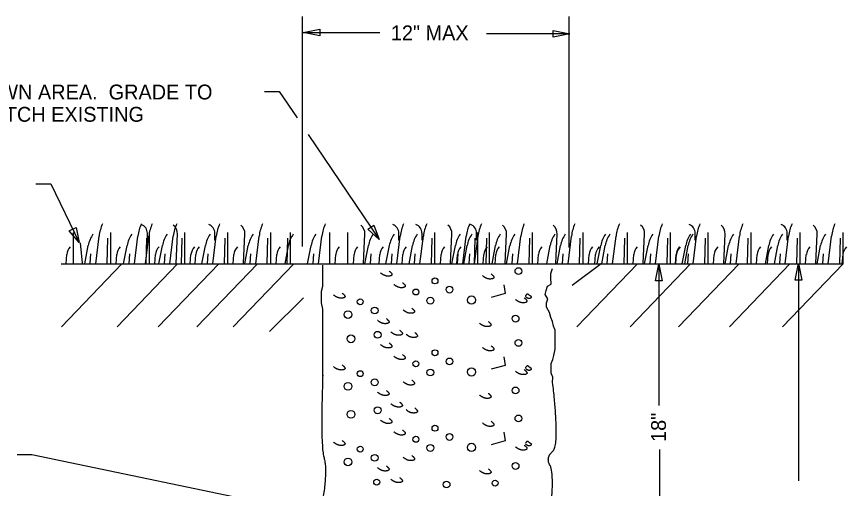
# Model space of a CAD drawing. Extents: x 10310.4 to 10401.1, y 10100.5 to 10143.6.
# Drawn here: x 10360.35 to 10397.58, y 10122.44 to 10143.62 of the extents above; entities that cross this region are included whole.
import ezdxf

# ---------------------------------------------------------------- set-up
doc = ezdxf.new("R2010")
doc.units = 0
for name, color, linetype in [('G-ANNO-TEXT', 7, 'Continuous'), ('G-DETL-LINE', 7, 'Continuous'), ('G-DETL-PATT', 7, 'Continuous')]:
    doc.layers.add(name, color=color, linetype=linetype)

msp = doc.modelspace()

# ---------------------------------------------------------------- linework, layer by layer
at = {"layer": 'G-ANNO-TEXT'}
for p, q in [((10373.185, 10133.298), (10373.185, 10143.615)), ((10385.137, 10133.255), (10385.137, 10143.615)), ((10373.209, 10142.899), (10376.655, 10142.899)), ((10385.175, 10142.836), (10381.434, 10142.836)), ((10371.471, 10140.249), (10372.138, 10140.249)), ((10372.138, 10140.249), (10372.935, 10139.065)), ((10373.435, 10138.323), (10376.614, 10133.607)), ((10361.22, 10136.112), (10361.887, 10136.112)), ((10361.887, 10136.112), (10363.16, 10133.474)), ((10389.164, 10132.497), (10389.164, 10126.153)), ((10395.422, 10132.539), (10395.422, 10122.775)), ((10389.206, 10120.468), (10389.206, 10124.176)), ((10360.378, 10123.964), (10361.045, 10123.964)), ((10361.045, 10123.964), (10377.733, 10120.481))]:
    msp.add_line(p, q, dxfattribs=at)
for points in [[(10373.959, 10142.749), (10373.209, 10142.899), (10373.959, 10143.049)], [(10384.425, 10142.986), (10385.175, 10142.836), (10384.425, 10142.686)], [(10376.38, 10134.253), (10376.614, 10133.607), (10376.103, 10134.067)], [(10363.02, 10134.147), (10363.16, 10133.474), (10362.72, 10134.002)], [(10389.014, 10131.747), (10389.164, 10132.497), (10389.314, 10131.747)], [(10395.272, 10131.789), (10395.422, 10132.539), (10395.572, 10131.789)]]:
    msp.add_lwpolyline(points, close=True, dxfattribs=at)
at = {"layer": 'G-DETL-LINE'}
for p, q in [((10362.356, 10132.519), (10373.219, 10132.519)), ((10373.219, 10132.519), (10385.16, 10132.519)), ((10385.16, 10132.519), (10397.427, 10132.519))]:
    msp.add_line(p, q, dxfattribs=at)
for points in [[(10362.911, 10132.519), (10362.911, 10133.917)], [(10364.575, 10132.519), (10364.575, 10133.917)], [(10366.223, 10133.581), (10366.223, 10133.886)], [(10366.315, 10132.519), (10366.315, 10133.917)], [(10367.506, 10132.542), (10367.567, 10133.856)], [(10367.903, 10132.519), (10367.903, 10133.917)], [(10369.25, 10133.581), (10369.25, 10133.886)], [(10369.83, 10132.519), (10369.83, 10133.917)], [(10370.532, 10132.542), (10370.593, 10133.856)], [(10371.753, 10132.519), (10371.753, 10133.917)], [(10372.645, 10132.519), (10372.645, 10133.917)], [(10374.401, 10132.519), (10374.401, 10133.917)], [(10375.216, 10132.519), (10375.216, 10133.917)], [(10375.919, 10132.542), (10375.98, 10133.856)], [(10377.501, 10133.581), (10377.501, 10133.886)], [(10378.539, 10133.581), (10378.539, 10133.886)], [(10379.119, 10132.519), (10379.119, 10133.917)], [(10379.821, 10132.542), (10379.882, 10133.856)], [(10380.99, 10133.581), (10380.99, 10133.886)], [(10381.042, 10132.519), (10381.042, 10133.917)], [(10381.57, 10132.519), (10381.57, 10133.917)], [(10382.272, 10132.542), (10382.333, 10133.856)], [(10383.494, 10132.519), (10383.494, 10133.917)], [(10384.54, 10132.542), (10384.601, 10133.856)], [(10385.761, 10132.519), (10385.761, 10133.917)], [(10387.763, 10132.519), (10387.763, 10133.917)], [(10388.465, 10132.542), (10388.526, 10133.856)], [(10389.686, 10132.519), (10389.686, 10133.917)], [(10390.795, 10133.581), (10390.795, 10133.886)], [(10391.375, 10132.519), (10391.375, 10133.917)], [(10392.077, 10132.542), (10392.138, 10133.856)], [(10393.298, 10132.519), (10393.298, 10133.917)], [(10394.924, 10133.581), (10394.924, 10133.886)], [(10395.504, 10132.519), (10395.504, 10133.917)], [(10396.206, 10132.542), (10396.267, 10133.856)], [(10397.427, 10132.519), (10397.427, 10133.917)], [(10363.201, 10133.459), (10363.293, 10132.542)], [(10363.903, 10132.519), (10364.056, 10133.764)], [(10364.422, 10132.519), (10364.453, 10133.672)], [(10365.643, 10132.519), (10365.796, 10133.764)], [(10366.132, 10132.519), (10366.284, 10133.764)], [(10366.162, 10132.519), (10366.193, 10133.672)], [(10367.231, 10132.519), (10367.384, 10133.764)], [(10367.75, 10132.519), (10367.78, 10133.672)], [(10369.158, 10132.519), (10369.311, 10133.764)], [(10369.677, 10132.519), (10369.708, 10133.672)], [(10371.082, 10132.519), (10371.234, 10133.764)], [(10371.601, 10132.519), (10371.631, 10133.672)], [(10372.492, 10132.519), (10372.523, 10133.672)], [(10373.897, 10132.519), (10374.049, 10133.764)], [(10377.409, 10132.519), (10377.562, 10133.764)], [(10378.447, 10132.519), (10378.6, 10133.764)], [(10378.966, 10132.519), (10378.997, 10133.672)], [(10380.371, 10132.519), (10380.523, 10133.764)], [(10380.89, 10132.519), (10380.92, 10133.672)], [(10380.899, 10132.519), (10381.051, 10133.764)], [(10381.418, 10132.519), (10381.448, 10133.672)], [(10382.822, 10132.519), (10382.975, 10133.764)], [(10383.341, 10132.519), (10383.371, 10133.672)], [(10385.09, 10132.519), (10385.242, 10133.764)], [(10385.609, 10132.519), (10385.639, 10133.672)], [(10387.091, 10132.519), (10387.244, 10133.764)], [(10387.61, 10132.519), (10387.641, 10133.672)], [(10389.014, 10132.519), (10389.167, 10133.764)], [(10389.533, 10132.519), (10389.564, 10133.672)], [(10390.704, 10132.519), (10390.856, 10133.764)], [(10391.222, 10132.519), (10391.253, 10133.672)], [(10392.627, 10132.519), (10392.779, 10133.764)], [(10393.146, 10132.519), (10393.176, 10133.672)], [(10394.832, 10132.519), (10394.985, 10133.764)], [(10395.351, 10132.519), (10395.381, 10133.672)], [(10396.755, 10132.519), (10396.908, 10133.764)], [(10397.274, 10132.519), (10397.305, 10133.672)], [(10363.415, 10132.519), (10363.567, 10133.336)], [(10365.155, 10132.519), (10365.308, 10133.336)], [(10366.742, 10132.519), (10366.895, 10133.336)], [(10368.67, 10132.519), (10368.823, 10133.336)], [(10370.593, 10132.519), (10370.746, 10133.336)], [(10372.394, 10132.519), (10372.547, 10133.336)], [(10373.408, 10132.519), (10373.561, 10133.336)], [(10375.98, 10132.519), (10376.132, 10133.336)], [(10376.921, 10132.519), (10377.074, 10133.336)], [(10377.959, 10132.519), (10378.111, 10133.336)], [(10379.882, 10132.519), (10380.035, 10133.336)], [(10380.41, 10132.519), (10380.563, 10133.336)], [(10381.683, 10132.519), (10381.836, 10133.336)], [(10382.333, 10132.519), (10382.486, 10133.336)], [(10384.135, 10132.519), (10384.287, 10133.336)], [(10384.601, 10132.519), (10384.754, 10133.336)], [(10386.402, 10132.519), (10386.555, 10133.336)], [(10386.603, 10132.519), (10386.755, 10133.336)], [(10388.526, 10132.519), (10388.679, 10133.336)], [(10390.215, 10132.519), (10390.368, 10133.336)], [(10390.327, 10132.519), (10390.48, 10133.336)], [(10392.138, 10132.519), (10392.291, 10133.336)], [(10393.94, 10132.519), (10394.092, 10133.336)], [(10394.343, 10132.519), (10394.496, 10133.336)], [(10396.267, 10132.519), (10396.419, 10133.336)], [(10362.574, 10132.519), (10362.605, 10132.939)], [(10363.659, 10132.519), (10363.69, 10132.97)], [(10364.819, 10132.519), (10364.85, 10132.939)], [(10365.399, 10132.519), (10365.43, 10132.97)], [(10366.559, 10132.519), (10366.59, 10132.939)], [(10366.987, 10132.519), (10367.017, 10132.97)], [(10368.147, 10132.519), (10368.177, 10132.939)], [(10368.365, 10132.519), (10368.395, 10132.939)], [(10368.914, 10132.519), (10368.945, 10132.97)], [(10370.074, 10132.519), (10370.105, 10132.939)], [(10370.837, 10132.519), (10370.868, 10132.97)], [(10371.998, 10132.519), (10372.028, 10132.939)], [(10373.653, 10132.519), (10373.683, 10132.97)], [(10374.645, 10132.519), (10374.676, 10132.939)], [(10375.461, 10132.519), (10375.491, 10132.939)], [(10376.224, 10132.519), (10376.254, 10132.97)], [(10376.616, 10132.519), (10376.646, 10132.939)], [(10377.165, 10132.519), (10377.196, 10132.97)], [(10377.654, 10132.519), (10377.684, 10132.939)], [(10378.203, 10132.519), (10378.234, 10132.97)], [(10379.363, 10132.519), (10379.394, 10132.939)], [(10380.105, 10132.519), (10380.135, 10132.939)], [(10380.126, 10132.519), (10380.157, 10132.97)], [(10380.654, 10132.519), (10380.685, 10132.97)], [(10381.287, 10132.519), (10381.317, 10132.939)], [(10381.814, 10132.519), (10381.845, 10132.939)], [(10382.578, 10132.519), (10382.608, 10132.97)], [(10383.738, 10132.519), (10383.768, 10132.939)], [(10384.845, 10132.519), (10384.876, 10132.97)], [(10386.006, 10132.519), (10386.036, 10132.939)], [(10386.297, 10132.519), (10386.328, 10132.939)], [(10386.847, 10132.519), (10386.877, 10132.97)], [(10388.007, 10132.519), (10388.038, 10132.939)], [(10388.77, 10132.519), (10388.801, 10132.97)], [(10389.91, 10132.519), (10389.94, 10132.939)], [(10389.93, 10132.519), (10389.961, 10132.939)], [(10390.459, 10132.519), (10390.49, 10132.97)], [(10391.619, 10132.519), (10391.65, 10132.939)], [(10392.383, 10132.519), (10392.413, 10132.97)], [(10393.543, 10132.519), (10393.573, 10132.939)], [(10394.038, 10132.519), (10394.069, 10132.939)], [(10394.588, 10132.519), (10394.618, 10132.97)], [(10395.748, 10132.519), (10395.778, 10132.939)], [(10396.511, 10132.519), (10396.542, 10132.97)], [(10397.392, 10132.519), (10397.423, 10132.939)], [(10374.086, 10127.479), (10374.093, 10127.662), (10374.093, 10127.861), (10374.093, 10128.044), (10374.093, 10128.227), (10374.093, 10128.509), (10374.093, 10128.708), (10374.093, 10128.941), (10374.093, 10129.174), (10374.093, 10129.456), (10374.093, 10129.739), (10374.093, 10129.971), (10374.093, 10130.204), (10374.093, 10130.486), (10374.027, 10130.769), (10374.027, 10131.051), (10374.027, 10131.284), (10374.093, 10131.517), (10374.093, 10131.749), (10374.093, 10132.032), (10374.093, 10132.231), (10374.093, 10132.464)], [(10384.4, 10127.193), (10384.406, 10127.429), (10384.34, 10127.612), (10384.34, 10127.844), (10384.34, 10128.044), (10384.406, 10128.227), (10384.456, 10128.409), (10384.506, 10128.692), (10384.506, 10128.924), (10384.506, 10129.124), (10384.506, 10129.356), (10384.506, 10129.539), (10384.439, 10129.722), (10384.39, 10129.921), (10384.323, 10130.104), (10384.257, 10130.337), (10384.124, 10130.569), (10384.124, 10130.769), (10384.19, 10130.952), (10384.057, 10131.134), (10384.107, 10131.317), (10384.174, 10131.517), (10384.34, 10131.6), (10384.323, 10131.882), (10384.323, 10132.081), (10384.39, 10132.314)]]:
    msp.add_lwpolyline(points, dxfattribs=at)
for centre, radius, start, end in [((10365.967, 10133.53), 1.926, 155.9651, 173.0105), ((10367.707, 10133.53), 1.926, 155.9651, 173.0105), ((10365.799, 10133.886), 0.424, 0, 69.3471), ((10368.196, 10133.53), 1.926, 155.9651, 173.0105), ((10369.295, 10133.53), 1.926, 155.9651, 173.0105), ((10367.092, 10133.878), 0.475, 357.3391, 52.176), ((10368.825, 10133.886), 0.424, 0, 69.3471), ((10371.222, 10133.53), 1.926, 155.9651, 173.0105), ((10370.119, 10133.878), 0.475, 357.3391, 52.176), ((10373.146, 10133.53), 1.926, 155.9651, 173.0105), ((10375.961, 10133.53), 1.926, 155.9651, 173.0105), ((10375.505, 10133.878), 0.475, 357.3391, 52.176), ((10377.077, 10133.886), 0.424, 0, 69.3471), ((10379.473, 10133.53), 1.926, 155.9651, 173.0105), ((10378.114, 10133.886), 0.424, 0, 69.3471), ((10380.511, 10133.53), 1.926, 155.9651, 173.0105), ((10379.408, 10133.878), 0.475, 357.3391, 52.176), ((10382.435, 10133.53), 1.926, 155.9651, 173.0105), ((10380.566, 10133.886), 0.424, 0, 69.3471), ((10382.962, 10133.53), 1.926, 155.9651, 173.0105), ((10381.859, 10133.878), 0.475, 357.3391, 52.176), ((10384.886, 10133.53), 1.926, 155.9651, 173.0105), ((10384.127, 10133.878), 0.475, 357.3391, 52.176), ((10387.154, 10133.53), 1.926, 155.9651, 173.0105), ((10389.155, 10133.53), 1.926, 155.9651, 173.0105), ((10388.052, 10133.878), 0.475, 357.3391, 52.176), ((10391.078, 10133.53), 1.926, 155.9651, 173.0105), ((10390.371, 10133.886), 0.424, 0, 69.3471), ((10392.767, 10133.53), 1.926, 155.9651, 173.0105), ((10391.664, 10133.878), 0.475, 357.3391, 52.176), ((10394.691, 10133.53), 1.926, 155.9651, 173.0105), ((10394.499, 10133.886), 0.424, 0, 69.3471), ((10396.896, 10133.53), 1.926, 155.9651, 173.0105), ((10395.792, 10133.878), 0.475, 357.3391, 52.176), ((10398.819, 10133.53), 1.926, 155.9651, 173.0105), ((10364.919, 10133.084), 1.375, 145.8509, 169.4213), ((10366.659, 10133.084), 1.375, 145.8509, 169.4213), ((10368.247, 10133.084), 1.375, 145.8509, 169.4213), ((10370.174, 10133.084), 1.375, 145.8509, 169.4213), ((10372.098, 10133.084), 1.375, 145.8509, 169.4213), ((10373.899, 10133.084), 1.375, 145.8509, 169.4213), ((10374.913, 10133.084), 1.375, 145.8509, 169.4213), ((10377.484, 10133.084), 1.375, 145.8509, 169.4213), ((10378.425, 10133.084), 1.375, 145.8509, 169.4213), ((10379.463, 10133.084), 1.375, 145.8509, 169.4213), ((10381.386, 10133.084), 1.375, 145.8509, 169.4213), ((10381.914, 10133.084), 1.375, 145.8509, 169.4213), ((10383.188, 10133.084), 1.375, 145.8509, 169.4213), ((10383.838, 10133.084), 1.375, 145.8509, 169.4213), ((10385.639, 10133.084), 1.375, 145.8509, 169.4213), ((10386.105, 10133.084), 1.375, 145.8509, 169.4213), ((10387.907, 10133.084), 1.375, 145.8509, 169.4213), ((10388.107, 10133.084), 1.375, 145.8509, 169.4213), ((10390.03, 10133.084), 1.375, 145.8509, 169.4213), ((10391.719, 10133.084), 1.375, 145.8509, 169.4213), ((10391.831, 10133.084), 1.375, 145.8509, 169.4213), ((10393.643, 10133.084), 1.375, 145.8509, 169.4213), ((10395.444, 10133.084), 1.375, 145.8509, 169.4213), ((10395.848, 10133.084), 1.375, 145.8509, 169.4213), ((10397.771, 10133.084), 1.375, 145.8509, 169.4213), ((10363.136, 10132.901), 0.533, 135.303, 175.8439), ((10365.381, 10132.901), 0.533, 135.303, 175.8439), ((10367.121, 10132.901), 0.533, 135.303, 175.8439), ((10368.709, 10132.901), 0.533, 135.303, 175.8439), ((10368.926, 10132.901), 0.533, 135.303, 175.8439), ((10370.636, 10132.901), 0.533, 135.303, 175.8439), ((10372.559, 10132.901), 0.533, 135.303, 175.8439), ((10375.207, 10132.901), 0.533, 135.303, 175.8439), ((10376.023, 10132.901), 0.533, 135.303, 175.8439), ((10377.178, 10132.901), 0.533, 135.303, 175.8439), ((10378.215, 10132.901), 0.533, 135.303, 175.8439), ((10379.925, 10132.901), 0.533, 135.303, 175.8439), ((10380.667, 10132.901), 0.533, 135.303, 175.8439), ((10381.848, 10132.901), 0.533, 135.303, 175.8439), ((10382.376, 10132.901), 0.533, 135.303, 175.8439), ((10384.3, 10132.901), 0.533, 135.303, 175.8439), ((10386.567, 10132.901), 0.533, 135.303, 175.8439), ((10386.859, 10132.901), 0.533, 135.303, 175.8439), ((10388.569, 10132.901), 0.533, 135.303, 175.8439), ((10390.472, 10132.901), 0.533, 135.303, 175.8439), ((10390.492, 10132.901), 0.533, 135.303, 175.8439), ((10392.181, 10132.901), 0.533, 135.303, 175.8439), ((10394.105, 10132.901), 0.533, 135.303, 175.8439), ((10394.6, 10132.901), 0.533, 135.303, 175.8439), ((10396.31, 10132.901), 0.533, 135.303, 175.8439), ((10397.954, 10132.901), 0.533, 135.303, 175.8439)]:
    msp.add_arc(centre, radius, start, end, dxfattribs=at)
msp.add_open_spline([(10374.087, 10127.521), (10373.979, 10124.368), (10374.304, 10123.282), (10373.87, 10120.566), (10374.521, 10118.175), (10374.413, 10116.763), (10374.956, 10115.893), (10374.196, 10114.372), (10374.739, 10110.787), (10377.887, 10111.33), (10380.275, 10110.352), (10382.12, 10111.33), (10383.64, 10111.656), (10384.509, 10113.829), (10383.966, 10118.284), (10384.509, 10123.065), (10384.075, 10123.825), (10384.726, 10124.368), (10384.4, 10127.193)], degree=2, dxfattribs=at)
at = {"layer": 'G-DETL-PATT'}
for p, q in [((10365.077, 10132.518), (10362.363, 10129.693)), ((10367.574, 10132.518), (10364.86, 10129.693)), ((10369.419, 10132.518), (10366.705, 10129.693)), ((10371.156, 10132.518), (10368.442, 10129.693)), ((10372.784, 10132.518), (10370.071, 10129.693)), ((10386.571, 10132.518), (10385.269, 10131.54)), ((10388.2, 10132.518), (10385.486, 10129.693)), ((10390.588, 10132.518), (10387.874, 10129.693)), ((10392.759, 10132.518), (10390.045, 10129.693)), ((10395.039, 10132.518), (10392.325, 10129.693)), ((10397.427, 10132.518), (10394.713, 10129.693)), ((10382.207, 10131.573), (10382.264, 10131.178)), ((10373.219, 10130.996), (10371.699, 10129.475)), ((10382.264, 10131.178), (10381.643, 10131.008)), ((10382.207, 10128.349), (10382.264, 10127.954)), ((10382.264, 10127.954), (10381.643, 10127.785)), ((10382.207, 10124.96), (10382.264, 10124.565)), ((10382.264, 10124.565), (10381.643, 10124.395))]:
    msp.add_line(p, q, dxfattribs=at)
for centre, radius in [((10382.865, 10132.192), 0.152), ((10379.122, 10131.75), 0.133), ((10378.264, 10131.254), 0.133), ((10379.772, 10131.359), 0.152), ((10375.768, 10130.812), 0.133), ((10378.914, 10130.864), 0.152), ((10380.759, 10130.89), 0.184), ((10376.418, 10130.422), 0.152), ((10375.223, 10130.239), 0.174), ((10382.735, 10130.057), 0.152), ((10376.549, 10129.333), 0.152), ((10375.353, 10129.151), 0.174), ((10382.865, 10128.968), 0.152), ((10379.122, 10128.526), 0.133), ((10379.772, 10128.136), 0.152), ((10378.264, 10128.031), 0.133), ((10375.768, 10127.588), 0.133), ((10378.914, 10127.64), 0.152), ((10380.759, 10127.666), 0.184), ((10375.223, 10127.016), 0.174), ((10376.418, 10127.198), 0.152), ((10382.735, 10126.834), 0.152), ((10376.549, 10125.943), 0.152), ((10375.353, 10125.761), 0.174), ((10382.865, 10125.579), 0.152), ((10379.122, 10125.136), 0.133), ((10379.772, 10124.746), 0.152), ((10378.264, 10124.641), 0.133), ((10375.768, 10124.199), 0.133), ((10378.914, 10124.251), 0.152), ((10380.759, 10124.277), 0.184), ((10375.223, 10123.626), 0.174), ((10376.418, 10123.809), 0.152), ((10382.735, 10123.444), 0.152), ((10376.508, 10122.718), 0.133), ((10379.642, 10122.612), 0.152), ((10381.819, 10122.674), 0.133)]:
    msp.add_circle(centre, radius, dxfattribs=at)
for points in [[(10377.069, 10132.192), (10377.303, 10132.01), (10376.887, 10131.932), (10376.679, 10132.114)], [(10381.644, 10132.062), (10381.878, 10131.88), (10381.462, 10131.802), (10381.254, 10131.984)], [(10377.667, 10131.671), (10377.901, 10131.489), (10377.485, 10131.411), (10377.277, 10131.593)], [(10374.963, 10131.202), (10375.197, 10131.02), (10374.781, 10130.942), (10374.573, 10131.124)], [(10383.125, 10130.994), (10383.359, 10130.812), (10382.943, 10130.734), (10382.735, 10130.916)], [(10383.177, 10131.047), (10383.307, 10130.943), (10383.489, 10131.021), (10383.385, 10131.073), (10383.255, 10131.203), (10383.177, 10131.073)], [(10378.082, 10130.526), (10378.316, 10130.344), (10377.9, 10130.266), (10377.692, 10130.448)], [(10376.938, 10130.057), (10377.172, 10129.875), (10376.756, 10129.797), (10376.548, 10129.979)], [(10381.513, 10129.927), (10381.747, 10129.745), (10381.331, 10129.667), (10381.123, 10129.849)], [(10377.536, 10129.537), (10377.77, 10129.355), (10377.354, 10129.277), (10377.146, 10129.459)], [(10378.212, 10129.437), (10378.446, 10129.255), (10378.031, 10129.177), (10377.823, 10129.359)], [(10377.069, 10128.968), (10377.303, 10128.786), (10376.887, 10128.708), (10376.679, 10128.89)], [(10381.644, 10128.838), (10381.878, 10128.656), (10381.462, 10128.578), (10381.254, 10128.76)], [(10377.667, 10128.448), (10377.901, 10128.266), (10377.485, 10128.188), (10377.277, 10128.37)], [(10374.963, 10127.979), (10375.197, 10127.797), (10374.781, 10127.719), (10374.573, 10127.901)], [(10383.177, 10127.824), (10383.307, 10127.719), (10383.489, 10127.797), (10383.385, 10127.85), (10383.255, 10127.98), (10383.177, 10127.85)], [(10383.125, 10127.771), (10383.359, 10127.588), (10382.943, 10127.51), (10382.735, 10127.693)], [(10378.082, 10127.302), (10378.316, 10127.12), (10377.9, 10127.042), (10377.692, 10127.224)], [(10376.938, 10126.834), (10377.172, 10126.652), (10376.756, 10126.574), (10376.548, 10126.756)], [(10381.513, 10126.704), (10381.747, 10126.522), (10381.331, 10126.444), (10381.123, 10126.626)], [(10377.536, 10126.313), (10377.77, 10126.131), (10377.354, 10126.053), (10377.146, 10126.235)], [(10378.212, 10126.047), (10378.446, 10125.865), (10378.031, 10125.787), (10377.823, 10125.969)], [(10377.069, 10125.579), (10377.303, 10125.397), (10376.887, 10125.319), (10376.679, 10125.501)], [(10381.644, 10125.449), (10381.878, 10125.266), (10381.462, 10125.188), (10381.254, 10125.371)], [(10377.667, 10125.058), (10377.901, 10124.876), (10377.485, 10124.798), (10377.277, 10124.98)], [(10374.963, 10124.589), (10375.197, 10124.407), (10374.781, 10124.329), (10374.573, 10124.511)], [(10383.177, 10124.434), (10383.307, 10124.33), (10383.489, 10124.408), (10383.385, 10124.46), (10383.255, 10124.59), (10383.177, 10124.46)], [(10383.125, 10124.381), (10383.359, 10124.199), (10382.943, 10124.121), (10382.735, 10124.303)], [(10378.082, 10123.913), (10378.316, 10123.73), (10377.9, 10123.652), (10377.692, 10123.835)], [(10376.938, 10123.444), (10377.172, 10123.262), (10376.756, 10123.184), (10376.548, 10123.366)], [(10381.513, 10123.314), (10381.747, 10123.132), (10381.331, 10123.054), (10381.123, 10123.236)], [(10377.536, 10122.924), (10377.77, 10122.742), (10377.354, 10122.664), (10377.146, 10122.846)]]:
    msp.add_open_spline(points, degree=2, dxfattribs=at)

# ---------------------------------------------------------------- texts
at = {"layer": 'G-ANNO-TEXT'}
for s, height, p in [('12" MAX', 0.6667, (10377.143, 10142.551)), ('LAWN AREA.  GRADE TO', 0.66667, (10358.489, 10139.895)), ('MATCH EXISTING', 0.66667, (10358.489, 10138.895))]:
    msp.add_text(s, height=height, dxfattribs=at).set_placement(p)
msp.add_text('18"', height=0.6667, rotation=90, dxfattribs=at).set_placement((10389.482, 10124.523))

doc.saveas('drawing.dxf')
